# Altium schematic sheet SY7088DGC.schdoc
size 127 x 101 mm
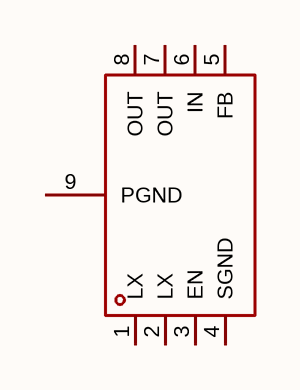
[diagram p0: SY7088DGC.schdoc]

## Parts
U?  sy7088dgc  [DFN-8_L3.0-W2.0-P0.50-BL-EP]  (value not drawn)

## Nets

Not connected (* = marked no-connect by the designer): U? 1(LX) 2(LX) 3(EN) 4(SGND) 5(FB) 6(IN) 7(OUT) 8(OUT) 9(PGND)

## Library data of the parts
U? = sy7088dgc: 功能类型:升压型;工作电压:2.3V~5.25V;输出电压:2.5V~5.5V;输出电流:3A;输出类型:可调;; Manufacturer: Silergy(矽力杰); AddInBom: yes; ModelId: 5f31edf22e934671a77503961025643c; ModelName: DFN-8_L3.0-W2.0-H0.8-P0.50; ModelTransform: 78.74,118.8974,0,0,0,0,0,0,0; Function: 升压型; Output Current: 3A; Frequency - Switching: 1MHz; Synchronous Rectifier: 是; Number of Outputs: 1; Topology: 升压式; Quiescent Current: 2uA; Switch tube (built-in/external): 内置; Output Type: 可调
